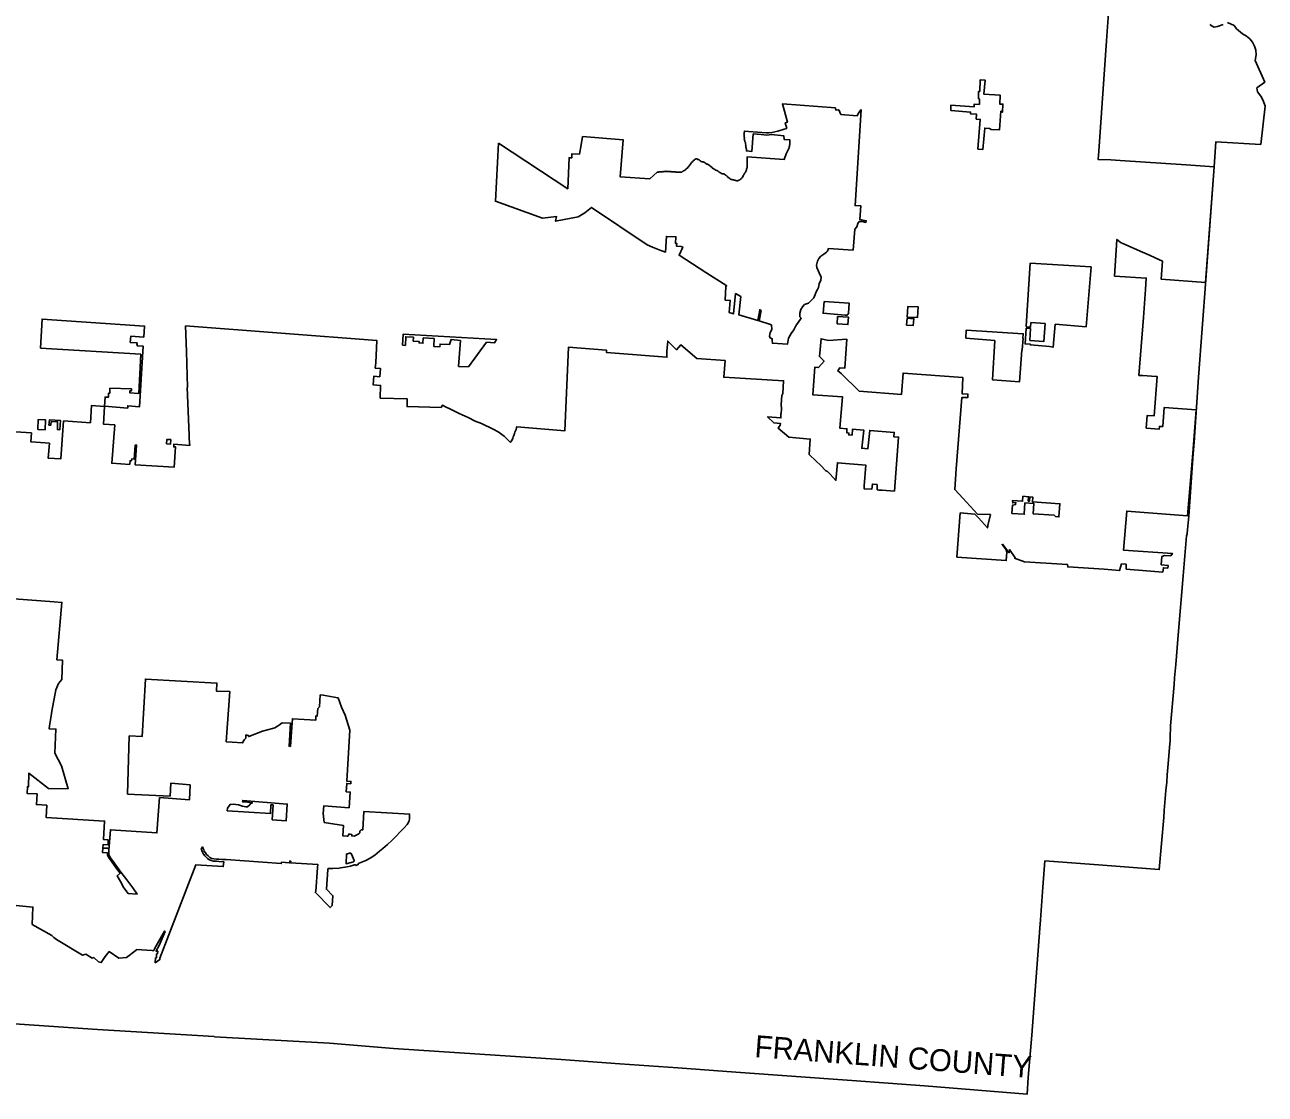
# Model space of a CAD drawing. Extents: x 1674899 to 2057726, y 653888 to 988278.
# Drawn here: x 1831756 to 1888218, y 653888 to 702553 of the extents above; entities that cross this region are included whole.
import ezdxf

# ---------------------------------------------------------------- set-up
doc = ezdxf.new("R2010")
doc.units = 0
for name, color, linetype in [('GM_X_Adjacent_County', 7, 'Continuous'), ('GM_X_Adjacent_County_Text', 7, 'Continuous'), ('GM_X_Corporation', 7, 'Continuous')]:
    doc.layers.add(name, color=color, linetype=linetype)

msp = doc.modelspace()

# ---------------------------------------------------------------- linework, layer by layer
at = {"layer": 'GM_X_Adjacent_County'}
msp.add_lwpolyline([(1881125, 703749), (1880996, 701827), (1880648, 696807), (1880621, 696420), (1881199, 696408), (1881620, 696382), (1884619, 696174), (1885889, 696091), (1885509, 690950), (1885182, 686522), (1884997, 683795), (1885000, 683743), (1884928, 682838), (1884830, 681510), (1884735, 680195), (1884687, 679579), (1884665, 679383), (1884630, 679290), (1884479, 677480), (1884260, 674783), (1884177, 673820), (1884153, 673436), (1884120, 673132), (1884093, 672829), (1884077, 672538), (1883910, 670644), (1883888, 670099), (1883896, 670058), (1883889, 669973), (1883877, 669831), (1883785, 668758), (1883760, 668427), (1883733, 668091), (1883700, 667709), (1883625, 666796), (1883609, 666477), (1883392, 664110), (1880829, 664311), (1878189, 664504), (1878096, 663311), (1877984, 661828), (1877958, 661450), (1877649, 657393), (1877591, 656580), (1877433, 654641), (1877380, 653888), (1872712, 654264), (1869398, 654514), (1864124, 654894), (1861474, 655088), (1858836, 655268), (1856984, 655410), (1856164, 655463), (1848544, 655971), (1845619, 656217), (1840391, 656502), (1840376, 656506), (1835058, 656829), (1829957, 657174)], dxfattribs=at)
at = {"layer": 'GM_X_Corporation'}
for points in [[(1886505, 702653), (1886798, 702522), (1886919, 702370), (1887182, 702141), (1887362, 702036), (1887517, 701908), (1887635, 701768), (1887729, 701587), (1887797, 701407), (1887812, 701181), (1887759, 700927), (1888195, 699941), (1887838, 699683), (1887868, 699496), (1888021, 699310), (1888131, 699110), (1888218, 698844), (1888017, 697107), (1885972, 697232), (1885889, 696091), (1885499, 690829), (1883487, 690976), (1883536, 691803), (1883209, 691950), (1882955, 692063), (1882635, 692203), (1881732, 692594), (1881661, 692636), (1881623, 692665), (1881516, 692751), (1881470, 692785), (1881468, 692766), (1881365, 691115), (1882803, 691027), (1882764, 690512), (1882673, 689229), (1882468, 686598), (1882584, 686594), (1882627, 686593), (1883252, 686551), (1883301, 686548), (1883163, 684754), (1882847, 684778), (1882803, 684202), (1883396, 684157), (1883405, 684278), (1883554, 684266), (1883622, 685144), (1885074, 685033), (1884922, 683059), (1884685, 680213), (1881913, 680427), (1881764, 678652), (1883994, 678496), (1883917, 678381), (1883632, 678407), (1883518, 678355), (1883484, 677979), (1883801, 677954), (1883785, 677830), (1883584, 677846), (1883556, 677648), (1881896, 677782), (1881885, 678007), (1881682, 678023), (1881590, 677715), (1880882, 677776), (1879227, 677886), (1879225, 677990), (1877256, 678112), (1876809, 678286), (1876831, 678292), (1876575, 678675), (1876568, 678526), (1876554, 678545), (1876260, 678918), (1876244, 678906), (1876426, 678659), (1876450, 678559), (1876430, 678173), (1874185, 678331), (1874334, 680339), (1874999, 680290), (1875165, 680113), (1875576, 679657), (1875590, 679724), (1875593, 679738), (1875598, 679763), (1875711, 680268), (1875122, 680290), (1874447, 681012), (1874086, 681399), (1874157, 682347), (1874416, 685600), (1874679, 685587), (1874687, 685752), (1874424, 685765), (1874461, 686501), (1871735, 686705), (1871665, 685737), (1869741, 685884), (1868909, 686681), (1868771, 686799), (1868852, 686943), (1869076, 686927), (1869167, 688241), (1868345, 688180), (1868005, 688265), (1867936, 687454), (1868139, 687250), (1867891, 686955), (1867717, 686969), (1867633, 685710), (1868979, 685617), (1868858, 684195), (1869178, 684171), (1869167, 683987), (1869270, 683977), (1869263, 683892), (1869412, 683880), (1869435, 684154), (1869942, 684111), (1869856, 683280), (1870132, 683259), (1870216, 684093), (1871335, 684006), (1871321, 683808), (1871527, 683792), (1871344, 681336), (1870784, 681372), (1870634, 681382), (1870556, 681393), (1870553, 681633), (1870341, 681650), (1870314, 681422), (1869958, 681440), (1869964, 681569), (1870039, 682521), (1868748, 682620), (1868680, 681819), (1868422, 682109), (1868374, 682157), (1868335, 682179), (1868291, 682218), (1868224, 682261), (1867973, 682514), (1867775, 682701), (1867460, 682994), (1867508, 683699), (1866537, 683789), (1866043, 684203), (1866138, 684340), (1866150, 684410), (1865849, 684442), (1865565, 684718), (1866173, 684662), (1866174, 684871), (1866184, 684870), (1866199, 685075), (1866182, 685269), (1866216, 685678), (1866258, 685776), (1866295, 686357), (1863575, 686513), (1863635, 687276), (1862344, 687368), (1861611, 687984), (1861425, 687763), (1861021, 688163), (1860987, 687679), (1860987, 687588), (1860981, 687422), (1858232, 687641), (1858240, 687741), (1856501, 687880), (1856343, 684081), (1854149, 684264), (1854136, 684210), (1854118, 684142), (1854094, 684080), (1854068, 684014), (1854054, 683962), (1854036, 683910), (1854012, 683858), (1853990, 683800), (1853976, 683745), (1853960, 683695), (1853916, 683627), (1853870, 683563), (1853862, 683548), (1853573, 683837), (1853305, 684032), (1853083, 684145), (1852547, 684407), (1852261, 684521), (1851942, 684681), (1851532, 684863), (1851133, 685057), (1850904, 685171), (1850768, 685239), (1850703, 685135), (1849157, 685178), (1849167, 685528), (1847937, 685563), (1847953, 686145), (1847614, 686169), (1847642, 686558), (1847916, 686539), (1847942, 686913), (1847707, 686929), (1847728, 687165), (1847787, 688183), (1839078, 688849), (1839109, 687686), (1839160, 686044), (1839153, 686045), (1839233, 683876), (1839237, 683787), (1839243, 683684), (1839249, 683611), (1839258, 683516), (1839270, 683412), (1838541, 683471), (1838533, 683347), (1838619, 683342), (1838562, 682424), (1836786, 682534), (1836841, 683429), (1836781, 683431), (1836739, 682792), (1836622, 682800), (1836617, 682715), (1836547, 682719), (1836536, 682549), (1835717, 682600), (1835847, 684346), (1835331, 684383), (1835385, 685180), (1834787, 685224), (1834739, 684447), (1833520, 684530), (1833394, 682801), (1832825, 682832), (1832873, 683513), (1832464, 683548), (1832036, 683568), (1832057, 683978), (1830337, 684084)], [(1885696, 702574), (1885742, 702530), (1885811, 702491), (1885899, 702452), (1886052, 702483), (1886301, 702566)], [(1831279, 676430), (1833096, 676292), (1833443, 676266), (1833220, 673658), (1833467, 673640), (1833434, 672761), (1833283, 672584), (1833173, 672288), (1833085, 671876), (1833003, 671416), (1832946, 671021), (1832883, 670647), (1832863, 670515), (1833173, 670502), (1833129, 669403), (1833432, 668828), (1833725, 667789), (1832832, 667797), (1831945, 668503), (1831927, 667875), (1831874, 667878), (1831856, 667578), (1832313, 667551), (1832283, 667067), (1832752, 667038), (1832725, 666484), (1835390, 666313), (1835341, 665474), (1835554, 665456), (1835544, 665236), (1835325, 665251), (1835312, 665101), (1835531, 665087), (1835531, 665067), (1835311, 665081), (1835298, 664882), (1835526, 664868), (1835524, 664780), (1835526, 664761), (1835534, 664732), (1835571, 664680), (1835694, 664503), (1835826, 664305), (1835933, 664158), (1836095, 663953), (1835954, 663820), (1836119, 663570), (1836264, 663286), (1836455, 663025), (1836867, 662988), (1836671, 663278), (1836402, 663637), (1836133, 663996), (1835831, 664420), (1835664, 664648), (1835602, 664750), (1835586, 664820), (1835588, 664971), (1835652, 665922), (1837770, 665776), (1837890, 667386), (1839249, 667283), (1839283, 667963), (1838398, 668037), (1838370, 667454), (1836435, 667543), (1836512, 670195), (1837091, 670161), (1837244, 672782), (1840502, 672598), (1840487, 672226), (1841095, 672208), (1840928, 669924), (1841193, 669907), (1841670, 669872), (1841733, 669978), (1841760, 670027), (1841820, 670091), (1841822, 670234), (1841925, 670207), (1841947, 670164), (1842571, 670405), (1843028, 670525), (1843135, 670565), (1843258, 670631), (1843349, 670689), (1843468, 670784), (1843847, 670779), (1843787, 669720), (1843847, 669716), (1843911, 670587), (1843939, 670971), (1844999, 670902), (1845010, 671101), (1845070, 671097), (1845087, 671434), (1845173, 671522), (1845202, 672061), (1845339, 672041), (1845998, 671924), (1846020, 671920), (1846177, 671505), (1846341, 671129), (1846554, 670450), (1846417, 668127), (1846599, 668118), (1846591, 668018), (1846408, 668027), (1846388, 667649), (1846569, 667637), (1846519, 666923), (1845364, 667003), (1845334, 666654), (1845390, 666258), (1846262, 666117), (1846226, 665648), (1846429, 665637), (1846458, 665637), (1846476, 665647), (1846487, 665681), (1846501, 665723), (1846566, 665719), (1846641, 665713), (1846639, 665643), (1846659, 665639), (1846749, 665636), (1846781, 665639), (1846936, 665727), (1846970, 665757), (1847013, 665789), (1847006, 665816), (1847008, 665855), (1847017, 665876), (1847031, 665892), (1847060, 665918), (1847099, 665924), (1847145, 665922), (1847195, 666756), (1849281, 666631), (1849253, 666605), (1849260, 666581), (1849271, 666516), (1849274, 666421), (1849256, 666323), (1849213, 666237), (1849156, 666160), (1849019, 666011), (1848463, 665434), (1848266, 665254), (1848053, 665068), (1847902, 664940), (1847682, 664768), (1847473, 664636), (1847286, 664528), (1846969, 664400), (1846941, 664380), (1846930, 664356), (1846932, 664333), (1846828, 664294), (1846822, 664305), (1846817, 664311), (1846810, 664318), (1846799, 664324), (1846792, 664326), (1846785, 664328), (1846779, 664328), (1846774, 664328), (1846765, 664326), (1846671, 664296), (1846569, 664268), (1846435, 664236), (1846331, 664215), (1846230, 664198), (1846120, 664183), (1846064, 664177), (1845775, 664157), (1845598, 664164), (1845585, 664162), (1845573, 664158), (1845568, 664155), (1845564, 664152), (1845561, 664149), (1845557, 664145), (1845554, 664141), (1845551, 664136), (1845548, 664126), (1845547, 664117), (1845488, 663214), (1845782, 662915), (1845754, 662480), (1845654, 662382), (1844970, 663080), (1845008, 663118), (1845079, 664197), (1845091, 664343), (1843852, 664410), (1843858, 664495), (1843818, 664498), (1843812, 664413), (1843436, 664446), (1843431, 664380), (1840918, 664570), (1840821, 664563), (1840721, 664572), (1840594, 664579), (1840488, 664588), (1840362, 664591), (1840275, 664616), (1840185, 664659), (1840141, 664689), (1840100, 664731), (1840029, 664794), (1839982, 664868), (1839927, 664954), (1839900, 665013), (1839881, 665072), (1839849, 665140), (1839788, 665035), (1839807, 664976), (1839839, 664907), (1839897, 664814), (1839952, 664729), (1840031, 664659), (1840076, 664613), (1840134, 664572), (1840239, 664522), (1840346, 664491), (1840483, 664488), (1840587, 664479), (1840810, 664467), (1840791, 664246), (1839539, 664319), (1837903, 660085), (1837906, 660012), (1837693, 659866), (1837711, 660090), (1837749, 660096), (1837749, 660174), (1837758, 660274), (1837789, 660277), (1837806, 660397), (1837736, 660385), (1837737, 660406), (1837871, 660656), (1838144, 661289), (1838115, 661308), (1837739, 660642), (1837730, 660637), (1837650, 660468), (1837643, 660467), (1837628, 660417), (1837560, 660424), (1836841, 660477), (1836820, 660441), (1836379, 660107), (1836032, 660072), (1835600, 660381), (1835410, 660160), (1835235, 659876), (1835111, 659911), (1834892, 660102), (1834817, 660072), (1834534, 660260), (1834378, 660215), (1833202, 660924), (1833136, 660973), (1833080, 661013), (1833037, 661066), (1832988, 661115), (1832094, 661612), (1832122, 662401), (1831365, 662472)]]:
    msp.add_lwpolyline(points, dxfattribs=at)
for points in [[(1873911, 698654), (1874808, 698580), (1874806, 698501), (1875072, 698489), (1875062, 698264), (1875250, 698251), (1875140, 696899), (1875369, 696881), (1875452, 697853), (1875666, 697841), (1875742, 697793), (1876123, 697773), (1876177, 698621), (1876259, 698571), (1876277, 698943), (1876132, 698947), (1876153, 699355), (1875415, 699391), (1875471, 700035), (1875458, 700036), (1875250, 700052), (1875222, 699525), (1875172, 699526), (1875166, 699200), (1875210, 699172), (1875206, 698932), (1874971, 698947), (1874965, 698815), (1873913, 698904)], [(1853314, 697174), (1853177, 694526), (1855327, 693748), (1855956, 693835), (1855915, 693614), (1856939, 693814), (1857245, 694003), (1857547, 694243), (1860080, 692538), (1860327, 692427), (1860710, 692289), (1860920, 692207), (1860963, 692923), (1861392, 692910), (1861373, 692607), (1861434, 692602), (1861427, 692478), (1861632, 692467), (1861702, 692436), (1861540, 692070), (1862757, 691285), (1863709, 690671), (1863676, 690644), (1863665, 690650), (1863632, 690025), (1863867, 690010), (1863822, 689460), (1864017, 689402), (1864114, 690321), (1864344, 690182), (1864258, 689355), (1865121, 689095), (1865214, 689588), (1865272, 689548), (1865183, 689079), (1865744, 688897), (1865760, 688694), (1865692, 688556), (1865656, 688381), (1865683, 688304), (1865782, 688264), (1865771, 688194), (1865790, 688059), (1866466, 688014), (1866514, 688300), (1866645, 688503), (1866769, 688671), (1866852, 688861), (1867103, 689199), (1867038, 689259), (1867038, 689436), (1867076, 689597), (1867160, 689719), (1867254, 689824), (1867432, 689887), (1867506, 689964), (1867676, 690125), (1867728, 690280), (1867771, 690404), (1867843, 690501), (1867883, 690594), (1867915, 690759), (1867991, 690927), (1868002, 691062), (1867911, 691263), (1867807, 691503), (1867799, 691618), (1867843, 691794), (1867903, 691921), (1867995, 692022), (1868130, 692119), (1868250, 692205), (1868289, 692258), (1868340, 692380), (1869458, 692303), (1869536, 693259), (1869622, 693353), (1869670, 693504), (1869736, 693599), (1869866, 693609), (1870041, 693559), (1870059, 693637), (1869771, 693687), (1869812, 694308), (1869550, 694325), (1869833, 698679), (1869814, 698680), (1869737, 698577), (1869660, 698456), (1869641, 698418), (1868907, 698473), (1868806, 698690), (1868687, 698662), (1868657, 698726), (1868651, 698772), (1866245, 698962), (1866336, 698628), (1866470, 698123), (1866374, 698093), (1866443, 697834), (1866328, 697798), (1866034, 697709), (1865767, 697650), (1865608, 697641), (1865518, 697637), (1864693, 697702), (1864510, 697716), (1864495, 697606), (1864481, 697579), (1864495, 697551), (1864495, 697524), (1864508, 697497), (1864508, 697469), (1864508, 697442), (1864522, 697415), (1864508, 697388), (1864522, 697360), (1864508, 697333), (1864536, 697279), (1864536, 697224), (1864563, 697197), (1864563, 697142), (1864576, 697115), (1864563, 697088), (1864576, 697060), (1864576, 696979), (1864590, 696951), (1864590, 696924), (1864604, 696897), (1864604, 696818), (1864851, 696794), (1864914, 697591), (1865278, 697562), (1865532, 697538), (1865750, 697559), (1866305, 697505), (1866315, 697341), (1866579, 697320), (1866574, 697105), (1866572, 697073), (1866566, 697034), (1866555, 696987), (1866543, 696952), (1866530, 696922), (1866419, 696689), (1866317, 696418), (1864641, 696550), (1864631, 696529), (1864645, 696501), (1864645, 696229), (1864645, 696106), (1864631, 696079), (1864631, 696052), (1864617, 696024), (1864604, 695983), (1864604, 695956), (1864590, 695929), (1864590, 695902), (1864563, 695847), (1864536, 695820), (1864522, 695793), (1864495, 695752), (1864481, 695724), (1864454, 695697), (1864454, 695670), (1864426, 695615), (1864399, 695588), (1864386, 695561), (1864331, 695533), (1864304, 695506), (1864222, 695465), (1864195, 695452), (1864167, 695452), (1864127, 695465), (1864099, 695465), (1864072, 695479), (1864045, 695479), (1864017, 695493), (1863990, 695493), (1863936, 695520), (1863908, 695520), (1863881, 695533), (1863854, 695561), (1863799, 695588), (1863772, 695602), (1863758, 695629), (1863731, 695643), (1863718, 695670), (1863690, 695683), (1863663, 695711), (1863636, 695724), (1863608, 695752), (1863581, 695765), (1863554, 695765), (1863527, 695779), (1863499, 695779), (1863390, 695833), (1863363, 695847), (1863309, 695902), (1863281, 695902), (1863254, 695929), (1863213, 695942), (1863172, 695970), (1863063, 696024), (1863049, 696052), (1863022, 696079), (1862995, 696092), (1862981, 696120), (1862954, 696120), (1862927, 696147), (1862899, 696161), (1862886, 696188), (1862831, 696215), (1862804, 696215), (1862750, 696242), (1862722, 696270), (1862640, 696311), (1862613, 696311), (1862586, 696324), (1862545, 696338), (1862504, 696365), (1862477, 696379), (1862450, 696406), (1862422, 696420), (1862395, 696420), (1862341, 696447), (1862313, 696447), (1862286, 696433), (1862245, 696420), (1862231, 696392), (1862204, 696392), (1862177, 696365), (1862163, 696338), (1862109, 696283), (1862095, 696256), (1862041, 696201), (1862041, 696174), (1862013, 696161), (1861986, 696106), (1861959, 696092), (1861945, 696065), (1861918, 696051), (1861904, 696024), (1861863, 695997), (1861850, 695970), (1861795, 695942), (1861754, 695915), (1861727, 695902), (1861700, 695874), (1861659, 695847), (1861427, 695847), (1861386, 695847), (1861359, 695861), (1861209, 695861), (1861182, 695874), (1861141, 695861), (1861113, 695874), (1860964, 695874), (1860936, 695888), (1860909, 695874), (1860854, 695874), (1860827, 695861), (1860800, 695874), (1860773, 695861), (1860636, 695861), (1860609, 695847), (1860536, 695847), (1860208, 695548), (1858861, 695628), (1858988, 697325), (1857149, 697469), (1857080, 697099), (1857004, 696664), (1856661, 696687), (1856651, 696499), (1856528, 696506), (1856467, 695096)], [(1877538, 688736), (1877359, 688749), (1877352, 688749), (1877349, 688749), (1877346, 688748), (1877344, 688747), (1877341, 688745), (1877339, 688743), (1877337, 688740), (1877335, 688737), (1877334, 688734), (1877288, 688032), (1877528, 688019), (1877528, 687986), (1878396, 687919), (1878563, 687879), (1878659, 688923), (1880062, 688815), (1880289, 691534), (1877521, 691700), (1877339, 688832), (1877340, 688828), (1877342, 688823), (1877345, 688818), (1877348, 688816), (1877350, 688815), (1877355, 688813), (1877541, 688800), (1877551, 689000), (1878199, 688955), (1878141, 688137), (1877510, 688192)], [(1868140, 689960), (1868096, 689429), (1869099, 689347), (1869133, 689343), (1869176, 689343), (1869210, 689358), (1869232, 689382), (1869245, 689427), (1869277, 689888)], [(1871926, 689253), (1872387, 689229), (1872422, 689719), (1871952, 689736)], [(1832464, 687840), (1837035, 687558), (1836948, 685780), (1836542, 685803), (1836542, 685903), (1836615, 685903), (1836615, 685985), (1835633, 686017), (1835619, 685784), (1835570, 685786), (1835562, 685601), (1835412, 685610), (1835386, 685195), (1836440, 685114), (1836443, 685215), (1836979, 685173), (1837144, 687929), (1836864, 687947), (1836871, 688007), (1836863, 688008), (1836870, 688078), (1836557, 688102), (1836582, 688381), (1837171, 688345), (1837205, 688840), (1832545, 689158)], [(1868757, 689286), (1868737, 688951), (1869226, 688915), (1869250, 689249)], [(1871924, 689203), (1871892, 688889), (1872196, 688876), (1872227, 689175)], [(1848956, 687970), (1849079, 687964), (1849099, 688358), (1849447, 688336), (1849436, 688161), (1849705, 688143), (1849701, 688074), (1849880, 688062), (1849896, 688306), (1850395, 688274), (1850372, 687920), (1850651, 687902), (1850659, 688026), (1851084, 687999), (1851161, 688227), (1851585, 688186), (1851500, 687011), (1851949, 686990), (1852778, 688109), (1853137, 688086), (1853231, 688228), (1848979, 688481)], [(1874584, 688288), (1875904, 688180), (1875799, 686401), (1877038, 686309), (1877141, 687752), (1877160, 687756), (1877207, 688277), (1877191, 688281), (1877206, 688492), (1874607, 688664)], [(1832343, 684135), (1832676, 684114), (1832703, 684575), (1832367, 684596)], [(1832955, 684508), (1833250, 684489), (1833241, 684130), (1833357, 684124), (1833383, 684539), (1832879, 684573), (1832857, 684338), (1832941, 684334)], [(1838211, 683480), (1838385, 683469), (1838398, 683677), (1838223, 683688)], [(1876687, 680319), (1877251, 680282), (1877284, 680798), (1877690, 680767), (1877654, 680304), (1878606, 680242), (1878675, 680170), (1878826, 680158), (1878872, 680756), (1877621, 680849), (1877640, 681058), (1877505, 681070), (1877488, 680871), (1877432, 680876), (1877450, 681075), (1877191, 681098), (1877175, 680872), (1876721, 680907), (1876720, 680863), (1876731, 680858), (1876728, 680798), (1876860, 680818), (1876852, 680720), (1876718, 680696)], [(1840973, 666785), (1842934, 666660), (1842960, 667059), (1843060, 667053), (1843016, 666374), (1843655, 666333), (1843703, 667089), (1841673, 667256), (1841669, 667188), (1841791, 667188), (1841899, 667182), (1842117, 667152), (1842021, 667099), (1841998, 667063), (1841893, 666961), (1841814, 666971), (1841669, 666997), (1841482, 667051), (1841233, 667091), (1841099, 667071), (1840981, 666907)], [(1846404, 664824), (1846380, 664376), (1846715, 664465), (1846720, 664468), (1846727, 664471), (1846733, 664476), (1846738, 664482), (1846742, 664487), (1846746, 664494), (1846748, 664503), (1846749, 664509), (1846749, 664514), (1846749, 664518), (1846748, 664522), (1846746, 664530), (1846628, 664815), (1846599, 664849), (1846574, 664862), (1846538, 664862), (1846444, 664832)]]:
    msp.add_lwpolyline(points, close=True, dxfattribs=at)

# ---------------------------------------------------------------- texts
at = {"layer": 'GM_X_Adjacent_County_Text'}
msp.add_text('FRANKLIN COUNTY', height=1000, rotation=355.6496, dxfattribs=at).set_placement((1864951, 655579))

doc.saveas('drawing.dxf')
